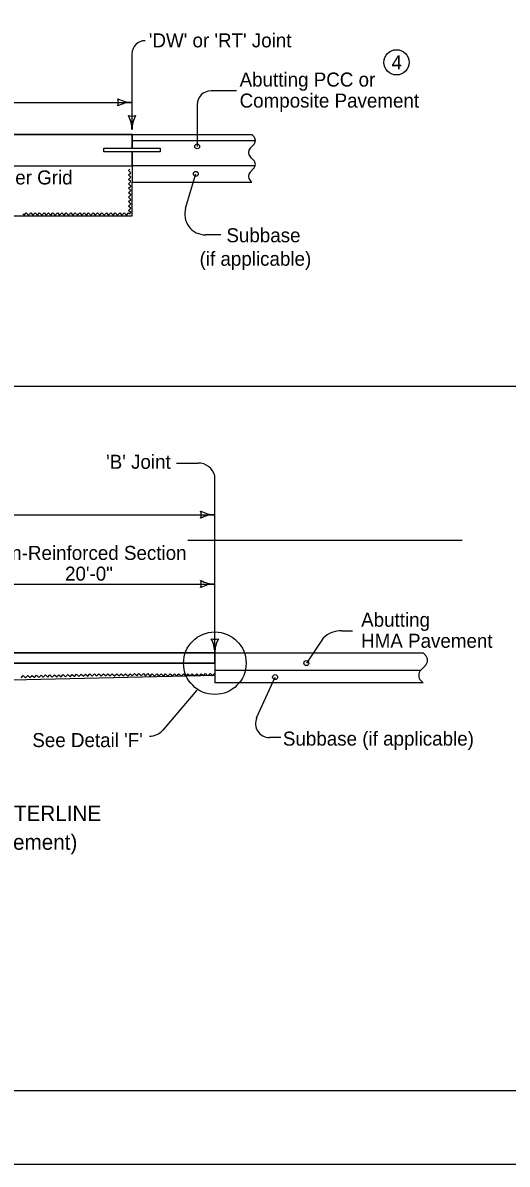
# Model space of a CAD drawing. Extents: x 10130 to 81668, y 5440 to 21644.
# Drawn here: x 15045 to 15735, y 5440 to 7067 of the extents above; entities that cross this region are included whole.
import ezdxf

# ---------------------------------------------------------------- set-up
doc = ezdxf.new("R2010")
doc.units = 0
for name, color, linetype in [('Cell', 7, 'Continuous'), ('dsnCellElements', 7, 'Continuous'), ('dsnShtPlotShapeBatchPrint', 7, 'Continuous'), ('dsnStdBlockModified', 7, 'Continuous'), ('dsnStdBlockNotModified', 7, 'Continuous'), ('dsnStdBorder', 7, 'Continuous')]:
    doc.layers.add(name, color=color, linetype=linetype)

msp = doc.modelspace()

# ---------------------------------------------------------------- linework, layer by layer
at = {"layer": 'Cell'}
msp.add_lwpolyline([(13803.2, 7554.1), (16938.2, 7554.1), (16938.2, 5544.1), (13803.2, 5544.1)], close=True, dxfattribs=at)
at = {"layer": 'dsnCellElements'}
for centre in [(15448.8, 6154.1), (15404.3, 6134.1)]:
    msp.add_circle(centre, 3.54, dxfattribs=at)
at = {"layer": 'dsnShtPlotShapeBatchPrint'}
msp.add_lwpolyline([(13698.7, 5439.6), (17042.7, 5439.6), (17042.7, 8023.6), (13698.7, 8023.6)], close=True, dxfattribs=at)
at = {"layer": 'dsnStdBlockNotModified'}
msp.add_line((13803.2, 6549.1), (16938.2, 6549.1), dxfattribs=at)
at = {"layer": 'dsnStdBorder'}
for p, q in [((15200.5, 6914.7), (15200.5, 7022.9)), ((15349.5, 6969.9), (15313, 6969.9)), ((14273.8, 6953.6), (15200.5, 6953.6)), ((15293.2, 6950.1), (15293.2, 6890.8)), ((15200.5, 6907.9), (14284, 6907.9)), ((14284, 6907.9), (15200.5, 6907.9)), ((15200.5, 6888.4), (15200.5, 6907.9)), ((15200.5, 6907.9), (15200.5, 6888.4)), ((15200.5, 6907.9), (15200.5, 6888.4)), ((15200.5, 6907.9), (15372.2, 6907.9)), ((15373.7, 6905.3), (15371.2, 6907.8)), ((15160.4, 6882.8), (15160.4, 6888.4)), ((15160.4, 6888.4), (15200.5, 6888.4)), ((15160.4, 6882.8), (15160.4, 6888.4)), ((15160.4, 6888.4), (15240.6, 6888.4)), ((15200.5, 6899), (15376.2, 6899)), ((15240.6, 6888.4), (15240.6, 6882.8)), ((15368.7, 6888.2), (15373.7, 6893.2)), ((15200.5, 6882.8), (15160.4, 6882.8)), ((15240.6, 6882.8), (15160.4, 6882.8)), ((15200.5, 6863.3), (15200.5, 6882.8)), ((15200.5, 6882.8), (15200.5, 6863.3)), ((15371.2, 6873.7), (15368.7, 6876.2)), ((15373.7, 6871.2), (15371.2, 6873.7)), ((14325.1, 6863.3), (15200.5, 6863.3)), ((14325.1, 6863.3), (15200.5, 6863.3)), ((15200.5, 6863.3), (15200.5, 6839.6)), ((15375.2, 6863.3), (15200.5, 6863.3)), ((15276.8, 6802.8), (15291.4, 6851.7)), ((15368.7, 6854.1), (15373.7, 6859.1)), ((15200.5, 6827.1), (15200.5, 6839.6)), ((15200.5, 6839.6), (15371.2, 6839.6)), ((15371.2, 6839.6), (15368.7, 6842.1)), ((15200.5, 6792), (15200.5, 6827.1)), ((14303.5, 6792), (15200.5, 6792)), ((15327, 6764.6), (15305.3, 6764.6)), ((15264, 6439.3), (15294.5, 6439.3)), ((15318.4, 6168.7), (15318.4, 6421)), ((14157.1, 6365.7), (15318.4, 6365.7)), ((15279.9, 6329.3), (15670.8, 6329.3)), ((14962, 6266.7), (15318.4, 6266.7)), ((15499.5, 6200.3), (15514.3, 6200.3)), ((15472.5, 6189.6), (15448.8, 6154.1)), ((14160.1, 6168.7), (15318.4, 6168.7)), ((15318.4, 6168.7), (14962, 6168.7)), ((15318.4, 6153.9), (15318.4, 6168.7)), ((15318.4, 6168.7), (15615.2, 6168.7)), ((15318.4, 6168.7), (15318.4, 6153.9)), ((15618.3, 6165.6), (15615.2, 6168.7)), ((15318.4, 6153.9), (14160.1, 6153.9)), ((14962, 6153.9), (15318.4, 6153.9)), ((15318.4, 6153.9), (15318.4, 6126.1)), ((15318.4, 6136.2), (14193.7, 6110.8)), ((15318.4, 6144), (15611.8, 6144)), ((15612, 6144.2), (15618.3, 6150.5)), ((15615, 6126.1), (15318.4, 6126.1)), ((15378, 6075.8), (15404.3, 6134.1)), ((15615.2, 6125.9), (15612, 6129.1)), ((15292.9, 6115.7), (15244.3, 6058.6)), ((15412.3, 6047.9), (15396.1, 6047.9))]:
    msp.add_line(p, q, dxfattribs=at)
for points in [[(15197.1, 6794.7), (15198.6, 6796.3), (15195.5, 6799.5), (15198.7, 6802.6), (15195.5, 6805.8), (15198.7, 6809), (15195.5, 6812.1), (15198.7, 6815.3), (15195.5, 6818.5), (15198.7, 6821.6), (15195.6, 6824.8), (15198.7, 6828), (15195.6, 6831.1), (15198.7, 6834.3), (15195.6, 6837.5), (15198.8, 6840.6), (15195.6, 6843.8), (15198.8, 6847), (15195.6, 6850.1), (15198.8, 6853.3), (15195.6, 6856.5), (15197.3, 6858.1)], [(15045, 6794.5), (15046.6, 6792.9), (15049.8, 6796.1), (15053, 6792.9), (15056.1, 6796.1), (15059.3, 6792.9), (15062.5, 6796.1), (15065.6, 6792.9), (15068.8, 6796), (15072, 6792.9), (15075.2, 6796), (15078.3, 6792.8), (15081.5, 6796), (15084.6, 6792.8), (15087.8, 6796), (15091, 6792.8), (15094.2, 6796), (15097.3, 6792.8), (15100.5, 6796), (15103.6, 6792.8), (15106.8, 6795.9), (15110, 6792.8), (15113.2, 6795.9), (15116.3, 6792.7), (15119.5, 6795.9), (15120.9, 6794.8)], [(15121.2, 6794.5), (15122.8, 6792.9), (15125.9, 6796.1), (15129.1, 6792.9), (15132.3, 6796.1), (15135.4, 6792.9), (15138.6, 6796.1), (15141.8, 6792.9), (15145, 6796), (15148.1, 6792.9), (15151.3, 6796), (15154.5, 6792.8), (15157.6, 6796), (15160.8, 6792.8), (15164, 6796), (15167.1, 6792.8), (15170.3, 6796), (15173.5, 6792.8), (15176.6, 6796), (15179.8, 6792.8), (15183, 6795.9), (15186.1, 6792.8), (15189.3, 6795.9), (15192.5, 6792.7), (15195.6, 6795.9), (15197.1, 6794.8)], [(15042.4, 6133.1), (15045.5, 6136.3), (15048.8, 6133.2), (15051.9, 6136.5), (15055.1, 6133.4), (15058.2, 6136.6), (15061.4, 6133.5), (15064.5, 6136.8), (15067.8, 6133.7), (15070.9, 6136.9), (15072.5, 6135.4)], [(15072.5, 6135.4), (15074.1, 6133.8), (15077.2, 6137.1), (15080.4, 6134), (15083.5, 6137.2), (15086.8, 6134.1), (15089.9, 6137.4), (15093.1, 6134.3), (15096.2, 6137.5), (15099.5, 6134.4), (15102.5, 6137.7), (15105.8, 6134.6), (15108.9, 6137.8), (15112.1, 6134.7), (15115.2, 6138), (15118.5, 6134.9), (15121.5, 6138.1), (15124.8, 6135), (15127.9, 6138.3), (15131.1, 6135.2), (15134.2, 6138.4), (15137.5, 6135.3), (15140.5, 6138.6), (15143.8, 6135.5), (15146.9, 6138.7), (15148.5, 6137.2)], [(15148.5, 6137.3), (15150.1, 6135.7), (15153.2, 6138.9), (15156.4, 6135.7), (15159.6, 6138.9), (15162.8, 6135.7), (15165.9, 6138.9), (15169.1, 6135.7), (15172.3, 6138.9), (15175.4, 6135.8), (15178.6, 6138.9), (15181.8, 6135.8), (15184.9, 6138.9), (15188.1, 6135.8), (15191.3, 6138.9), (15194.4, 6135.8), (15197.6, 6138.9), (15200.8, 6135.8), (15203.9, 6139), (15207.1, 6135.8), (15210.3, 6139), (15213.4, 6135.8), (15216.6, 6139), (15219.8, 6135.8), (15222.9, 6139), (15224.5, 6137.4)], [(15224.5, 6137.2), (15226.1, 6135.6), (15229.3, 6138.8), (15232.4, 6135.6), (15235.6, 6138.8), (15238.8, 6135.6), (15241.9, 6138.8), (15245.1, 6135.6), (15248.3, 6138.8), (15251.5, 6135.6), (15254.6, 6138.8), (15257.8, 6135.6), (15261, 6138.8), (15264.1, 6135.6), (15267.3, 6138.8), (15270.5, 6135.6), (15273.6, 6138.8), (15276.8, 6135.7), (15280, 6138.8), (15283.1, 6135.7), (15286.3, 6138.8), (15289.5, 6135.7), (15292.6, 6138.8), (15295.8, 6135.7), (15299, 6138.9), (15300.6, 6137.3)], [(15300.5, 6137.6), (15302.1, 6136), (15305.3, 6139.2), (15308.4, 6136), (15311.6, 6139.2), (15314.8, 6136), (15317.9, 6139.2), (15318.4, 6138.7)]]:
    msp.add_lwpolyline(points, dxfattribs=at)
for centre, radius in [((15577.2, 7010.6), 18), ((15293.2, 6890.8), 3.47), ((15291.4, 6851.7), 3.47), ((15318.4, 6153.9), 44.6)]:
    msp.add_circle(centre, radius, dxfattribs=at)
for centre, radius, start, end in [((15219, 7022.9), 18.6, 90, 180), ((15313, 6950.1), 19.8, 90, 180), ((15164.6, 6953.6), 16.5, 342.2666, 17.7333), ((15200.5, 6996.4), 42.7, 241.9275, 270), ((15164.6, 6953.6), 16.5, 342.2666, 17.7333), ((15200.5, 6996.4), 42.7, 241.9275, 270), ((15200.5, 6910.9), 42.7, 90, 118.0725), ((15200.5, 6910.9), 42.7, 90, 118.0725), ((15200.5, 6950.5), 16.5, 252.2666, 287.7333), ((15157.7, 6914.7), 42.7, 360, 28.0725), ((15200.5, 6950.5), 16.5, 252.2666, 287.7333), ((15157.7, 6914.7), 42.7, 360, 28.0725), ((15243.2, 6914.7), 42.7, 151.9275, 180), ((15243.2, 6914.7), 42.7, 151.9275, 180), ((15367.7, 6899.2), 8.53, 315, 45), ((15374.8, 6882.2), 8.53, 135, 225), ((15367.7, 6865.1), 8.53, 315, 45), ((15374.8, 6848.1), 8.53, 135, 225), ((15305.3, 6794.3), 29.7, 163.4172, 270), ((15294.5, 6414.5), 24.8, 15.0299, 90), ((15282.5, 6365.7), 16.5, 342.2666, 17.7333), ((15318.4, 6408.5), 42.7, 241.9275, 270), ((15318.4, 6323), 42.7, 90, 118.0725), ((15282.5, 6266.7), 16.5, 342.2666, 17.7333), ((15318.4, 6309.5), 42.7, 241.9275, 270), ((15318.4, 6224), 42.7, 90, 118.0725), ((15499.5, 6160.7), 39.6, 90, 132.998), ((15318.4, 6204.6), 16.5, 252.2666, 287.7333), ((15275.6, 6168.7), 42.7, 360, 28.0725), ((15361.1, 6168.7), 42.7, 151.9275, 180), ((15610.7, 6158), 10.7, 315, 45), ((15619.6, 6136.6), 10.7, 135, 225), ((15396.1, 6067.7), 19.8, 155.762, 270), ((15225.2, 6074.8), 25, 270, 319.6052)]:
    msp.add_arc(centre, radius, start, end, dxfattribs=at)

# ---------------------------------------------------------------- texts
at = {"layer": 'dsnStdBlockModified'}
for s, height, p in [("'DW' or 'RT' Joint", 20, (15224.4, 7032)), ('4', 20, (15570.1, 7000.6)), ('Abutting PCC or', 20, (15353.7, 6976.1)), ('Composite Pavement', 20, (15353.7, 6946.1)), ('Polymer Grid', 20, (14959.8, 6836.5)), ('Subbase', 20, (15334.9, 6754.1)), ('(if applicable)', 20, (15296.7, 6720.6)), ("'B' Joint", 20, (15163.6, 6431.1)), ('Non-Reinforced Section', 20, (14994.2, 6301.2)), ('20\'-0"', 20, (15105, 6271.6)), ('Abutting', 20, (15526.8, 6205.9)), ('HMA Pavement', 20, (15526.8, 6175.9)), ("See Detail 'F'", 20, (15058.4, 6034.3)), ('Subbase (if applicable)', 20, (15415.4, 6036.4)), ('(Abutting HMA Pavement)', 22, (14780.8, 5887.9))]:
    msp.add_text(s, height=height, dxfattribs=at).set_placement(p)
at = {"layer": 'dsnStdBorder'}
msp.add_text('SECTION THRU CENTERLINE', height=22, dxfattribs=at).set_placement((14741.3, 5928.8))

doc.saveas('drawing.dxf')
